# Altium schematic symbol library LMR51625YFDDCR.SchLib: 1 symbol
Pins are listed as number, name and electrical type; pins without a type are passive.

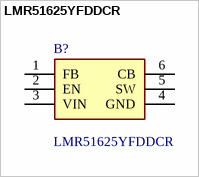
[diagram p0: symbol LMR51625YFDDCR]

## LMR51625YFDDCR
designator B?
Functional Safety-Capable  Documentation available to aid functional safety system design  Configured for rugged industrial applications:  4.3V to 60V input voltage range  2.5A or 3.5A continuous output current  Low operating quiescent current of 29uA  70ns minimum switching on time  400kHz amd 1.1MHz switching frequency  Frequency spread spectrum (PFM variant)  40C to 150C junction temperature range  96% maximum duty cycle  Monotonic start-up with prebiased output  Short-circu; Manufacturer_Name: Texas Instruments; Geometry.Height: 1.1mm
footprint SOT95P280X110-6N
pins: 1 FB, 2 EN, 3 VIN, 4 GND, 5 SW, 6 CB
